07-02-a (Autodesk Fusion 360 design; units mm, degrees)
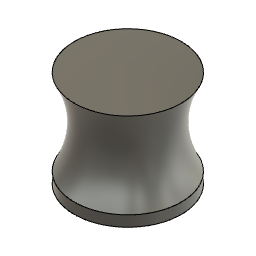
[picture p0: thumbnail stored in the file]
sketch "スケッチ1" plane through (0, 0, 0) normal (0, 1, 0) x axis (1, 0, 0)
  circle C1 centre (0, 0) radius 25
  point P1 (0, 0)
  point P2 (0, 0)
  coincident P1 P2
  dimension "d1" diameter C1 = 50
extrude "押し出し" new body sketch "スケッチ1" along normal blind 5
work_plane "作業平面1" AlongDistance 20
sketch "スケッチ2" plane through (0, 25, 0) normal (0, 1, 0) x axis (1, 0, 0)
  circle C1 centre (0, 0) radius 20
  point P1 (0, 0)
  point P2 (0, 0)
  coincident P1 P2
  dimension "d5" diameter C1 = 40
work_plane "作業平面2" AlongDistance 20
sketch "スケッチ3" plane through (0, 45, 0) normal (0, 1, 0) x axis (1, 0, 0)
  circle C1 centre (0, 0) radius 25
loft "ロフト" sketch "スケッチ2" + "スケッチ3"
